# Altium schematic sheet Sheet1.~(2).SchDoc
size A4; SheetNumber: 1; SheetTotal: 1
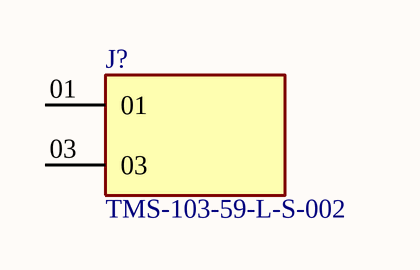
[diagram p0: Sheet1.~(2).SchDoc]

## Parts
J?  TMS-103-59-L-S-002  [SAMTEC_TMS-103-59-L-S-002]

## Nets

Not connected (* = marked no-connect by the designer): J? 01 03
